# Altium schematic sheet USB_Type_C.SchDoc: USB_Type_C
size A4; Date: Not used; ApprovedBy: Not used; CheckedBy: Not used; Author: Not used; CompanyName: STMicroelectronics; DrawnBy: Not used; Engineer: Not used; Organization: Not used; Address1: Not used; Address2: Not used; Address3: Not used; Address4: Not used; DocumentNumber: 7; Revision: Not used; SheetNumber: 7; SheetTotal: 9
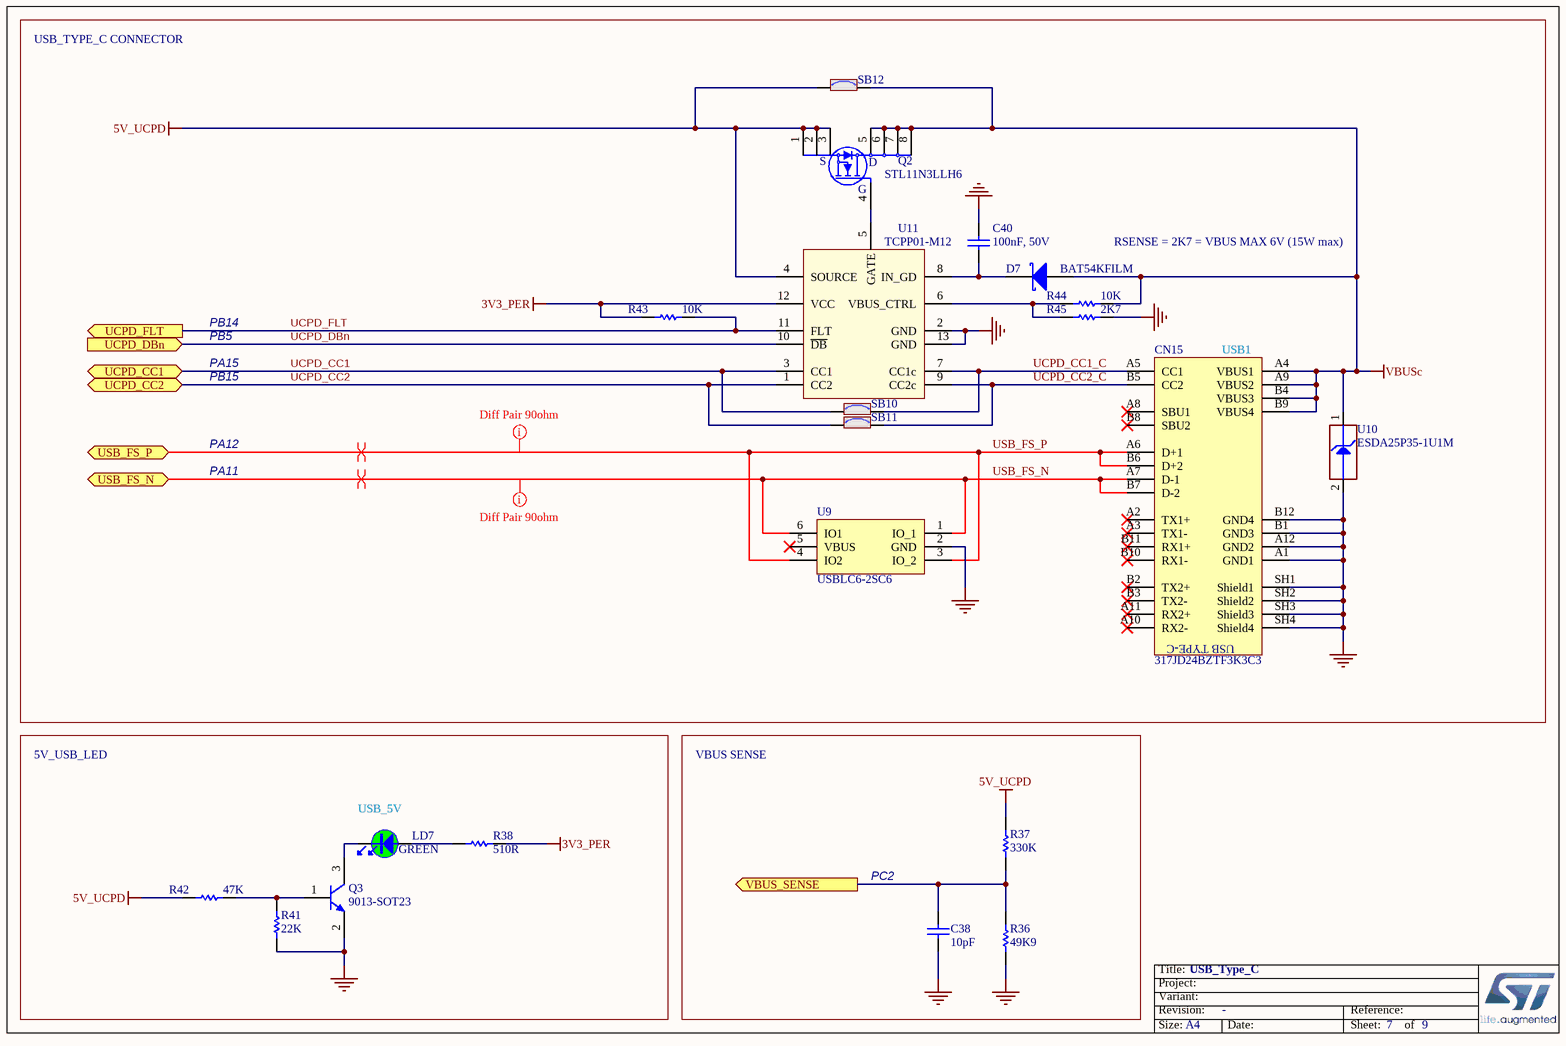
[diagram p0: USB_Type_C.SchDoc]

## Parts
C38  value 10pF  [C0603]
C40  value 100nF, 50V  [C0603]  (hidden comment: Capacitor)
CN15  value 317JD24BZTF3K3C3  [CON_USB-TYPEC_COXOC_317JD24BZTF3K3C3]  (hidden comment: USB_TYPE_C_Receptacle_317JD24BZTF3K3C3)
D7  value BAT54KFILM  [DIO_SOD523_1A_2K]  (hidden comment: SCHOTTKY_1A_2K)
LD7  value GREEN  [LED_0603_GREEN]
Q2  STL11N3LLH6  [MOS_POWERFLAT_3P3X3P3_P065]
Q3  value 9013-SOT23  [NPN_SOT23]
R36  value 49K9  [R0603]
R37  value 330K  [R0603]
R38  value 510R  [R0603]
R41  value 22K  [R0603]
R42  value 47K  [R0603]
R43  value 10K  [R0603]  (hidden comment: Resistor)
R44  value 10K  [R0603]  (hidden comment: Resistor)
R45  value 2K7  [R0603]  (hidden comment: Resistor)
SB10  (no value)  [SOLDER-BRIDGE_R0603-0R]
SB11  (no value)  [SOLDER-BRIDGE_R0603-0R]
SB12  (no value)  [SOLDER-BRIDGE_R0603-0R]
U9  USBLC6-2SC6  [ESD_SOT23-6L]
U10  value ESDA25P35-1U1M  [ESD_QFN1610_2N_1K_2A]  (hidden comment: ESD-TRANSIL)
U11  TCPP01-M12  [ICC_QFN12L-EPAD_3X3_P050]

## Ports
UCPD_CC1 (bidir), UCPD_CC2 (bidir), UCPD_DBn, UCPD_FLT, USB_FS_N (bidir), USB_FS_P (bidir), VBUS_SENSE

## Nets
3V3_PER: R38.1 R43.2 U11.12(VCC)
5V_UCPD: Q2.1(S) Q2.2(S) Q2.3(S) R37.2 R42.1 SB12.1 U11.4(SOURCE)
GND: C38.1 C40.1 CN15.A1(GND1) CN15.A12(GND2) CN15.B1(GND3) CN15.B12(GND4) CN15.SH1(Shield1) CN15.SH2(Shield2) CN15.SH3(Shield3) CN15.SH4(Shield4) Q3.2(E) R36.1 R41.1 R45.1 U9.2(GND) U10.2(GND) U11.2(GND) U11.13(GND)
VBUSc: CN15.A4(VBUS1) CN15.A9(VBUS2) CN15.B4(VBUS3) CN15.B9(VBUS4) D7.1(A) Q2.5(D) Q2.6(D) Q2.7(D) Q2.8(D) R44.2 SB12.2 U10.1(IO1)
UCPD_CC1: SB10.1 U11.3(CC1) ; port UCPD_CC1
UCPD_CC1_C: CN15.A5(CC1) SB10.2 U11.7(CC1c)
UCPD_CC2: SB11.1 U11.1(CC2) ; port UCPD_CC2
UCPD_CC2_C: CN15.B5(CC2) SB11.2 U11.9(CC2c)
UCPD_DBn: U11.10(~{DB}) ; port UCPD_DBn
UCPD_FLT: R43.1 U11.11(FLT) ; port UCPD_FLT
USB_FS_N: CN15.A7(D-1) CN15.B7(D-2) U9.1(IO_1) U9.6(IO1) ; port USB_FS_N
USB_FS_P: CN15.A6(D+1) CN15.B6(D+2) U9.3(IO_2) U9.4(IO2) ; port USB_FS_P
VBUS_SENSE: C38.2 R36.2 R37.1 ; port VBUS_SENSE
NetC40_2: C40.2 D7.2(K) U11.8(IN_GD)
NetLD7_1: LD7.1 R38.2
NetLD7_2: LD7.2 Q3.3(C)
NetQ2_4: Q2.4(G) U11.5(GATE)
NetQ3_1: Q3.1(B) R41.2 R42.2
NetR44_1: R44.1 R45.2 U11.6(VBUS_CTRL)

Not connected (* = marked no-connect by the designer): CN15 A2(TX1+)* A3(TX1-)* A8(SBU1)* A10(RX2-)* A11(RX2+)* B2(TX2+)* B3(TX2-)* B8(SBU2)* B10(RX1-)* B11(RX1+)*; U9 5(VBUS)*

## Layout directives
mark named Diff Pair 90ohm: USB_FS_N, USB_FS_P
differential pair: USB_FS_N, USB_FS_P

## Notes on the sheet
- USB_TYPE_C CONNECTOR
- RSENSE = 2K7 = VBUS MAX 6V (15W max)
- PA15
- PB15
- PB14
- PB5
- (near CN15) USB1
- PA12
- PA11
- 5V_USB_LED
- VBUS SENSE
- (near LD7) USB_5V
- PC2

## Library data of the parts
C38 = MCD-00637: Capacitor, MLCC, 10pF, 50V, NPO, 5%, 0603, T=0,8mm; Manufacturer_Part_Number: CC0603JRNPO9BN100; Manufacturer: YAGEO; Provided_By: subcon; Initial_Board_Reference: MB1319
C40 = MCD-01099: Capacitor,100nF,50V,X7R,10%,0603; Manufacturer_Part_Number: CC0603KRX7R9BB104; Manufacturer: YAGEO; Provided_By: SUBCO
CN15 = MCD-01108: USB tyce C certified receptacle for 1.6mm pcb height; Part_Type: Connector; Manufacturer: CHANT SINCERE (COXOC); Provided_By: SUBCO
D7 = MCD-01677: Small signal Schottky diodes; Part_Type: Diode; Manufacturer: STMICROELECTRONICS; ECCN_US: EAR99; ECCN_EU: NEC; Provided_By: SUBCO
LD7 = MCD-00050: LED, Green, 0603; Part_Type: Display; Manufacturer_Part_Number: 19-213SYGC/S530-E2/TR8; Manufacturer: EVERLIGHT; ECCN_US: EAR99; ECCN_EU: NEC; Provided_By: Subcon; Initial_Board_Reference: MB1274
Q2 = MCD-01810: N-channel 30 V, 6 mΩ typ, 11 A STripFET™ H6, Power MOSFET in a PowerFLAT™ 3.3x3.3 package; Part_Type: IC; Manufacturer: STMICROELECTRONICS; ECCN_US: EAR99; ECCN_EU: NEC; Provided_By: SUBCO with ST control
Q3 = MCD-00073: NPN Bipolar Transistor; Part_Type: IC; Manufacturer_Part_Number: BSR14; Manufacturer: NXP; ECCN_US: EAR99; ECCN_EU: NEC; Provided_By: Subcon; Initial_Board_Reference: MB1274
R36 = MCD-01171: Resistor,49K9,0603,1%; Manufacturer_Part_Number: RC0603FR-0749K9L; Manufacturer: YAGEO; Provided_By: Subcon; Initial_Board_Reference: MB1397
R37 = MCD-00458: Resistor,330K,0603,1%,1/10W; Manufacturer_Part_Number: RC0603FR-07330KL; Manufacturer: YAGEO; Provided_By: Subcon
R38 = MCD-00225: Resistor,510R,0603,1%,1/10W; Manufacturer_Part_Number: RC0603FR-07510RL; Manufacturer: YAGEO; Provided_By: Subcon; Initial_Board_Reference: MB1319
R41 = MCD-00430: Resistor,22K,0603,1%,1/10W; Manufacturer_Part_Number: RC0603FR-0722KL; Manufacturer: YAGEO; Provided_By: Subcon
R42 = MCD-00222: Resistor,47K,0603,1%,1/10W; Manufacturer_Part_Number: RC0603FR-0747KL; Manufacturer: YAGEO; Provided_By: Subcon; Initial_Board_Reference: MB1319
R43 R44 = MCD-00220: Resistor,10K,0603,1%,1/10W; Manufacturer_Part_Number: RC0603FR-0710KL; Manufacturer: YAGEO; ECCN_US: EAR99; ECCN_EU: NEC; Provided_By: SUBCO
R45 = MCD-00218: Resistor,2K7,0603,1%,1/10W; Manufacturer_Part_Number: RC0603FR-072K7L; Manufacturer: YAGEO; BMS_Part_Number: 9129767; ECCN_US: EAR99; ECCN_EU: NEC; Provided_By: SUBCO
SB10-SB12 = MCD-00071: Solder Bridge ON; Part_Type: Mechanical; Provided_By: Subcon; Initial_Board_Reference: MB1274
U9 = MCD-00163: Very low capacitance ESD protection; Part_Type: IC; Manufacturer: STMICROELECTRONICS; BMS_Part_Number: 9151075; ECCN_US: EAR99; ECCN_EU: NEC; Provided_By: SUBCO with ST control
U10 = MCD-01207: High power Transient voltage suppressor:25V/35A EOS and ESD transients protection.; Part_Type: Diode; Manufacturer: STMICROELECTRONICS; BMS_Part_Number: 9179045; ECCN_US: EAR99; ECCN_EU: NEC; Provided_By: SUBCO with ST control
U11 = MCD-01809: USB Type-C Port Protection for USB Power Delivery, PPS compliant; Part_Type: IC; Manufacturer: STMICROELECTRONICS; ECCN_US: EAR99; ECCN_EU: NEC; Provided_By: SUBCO with ST control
